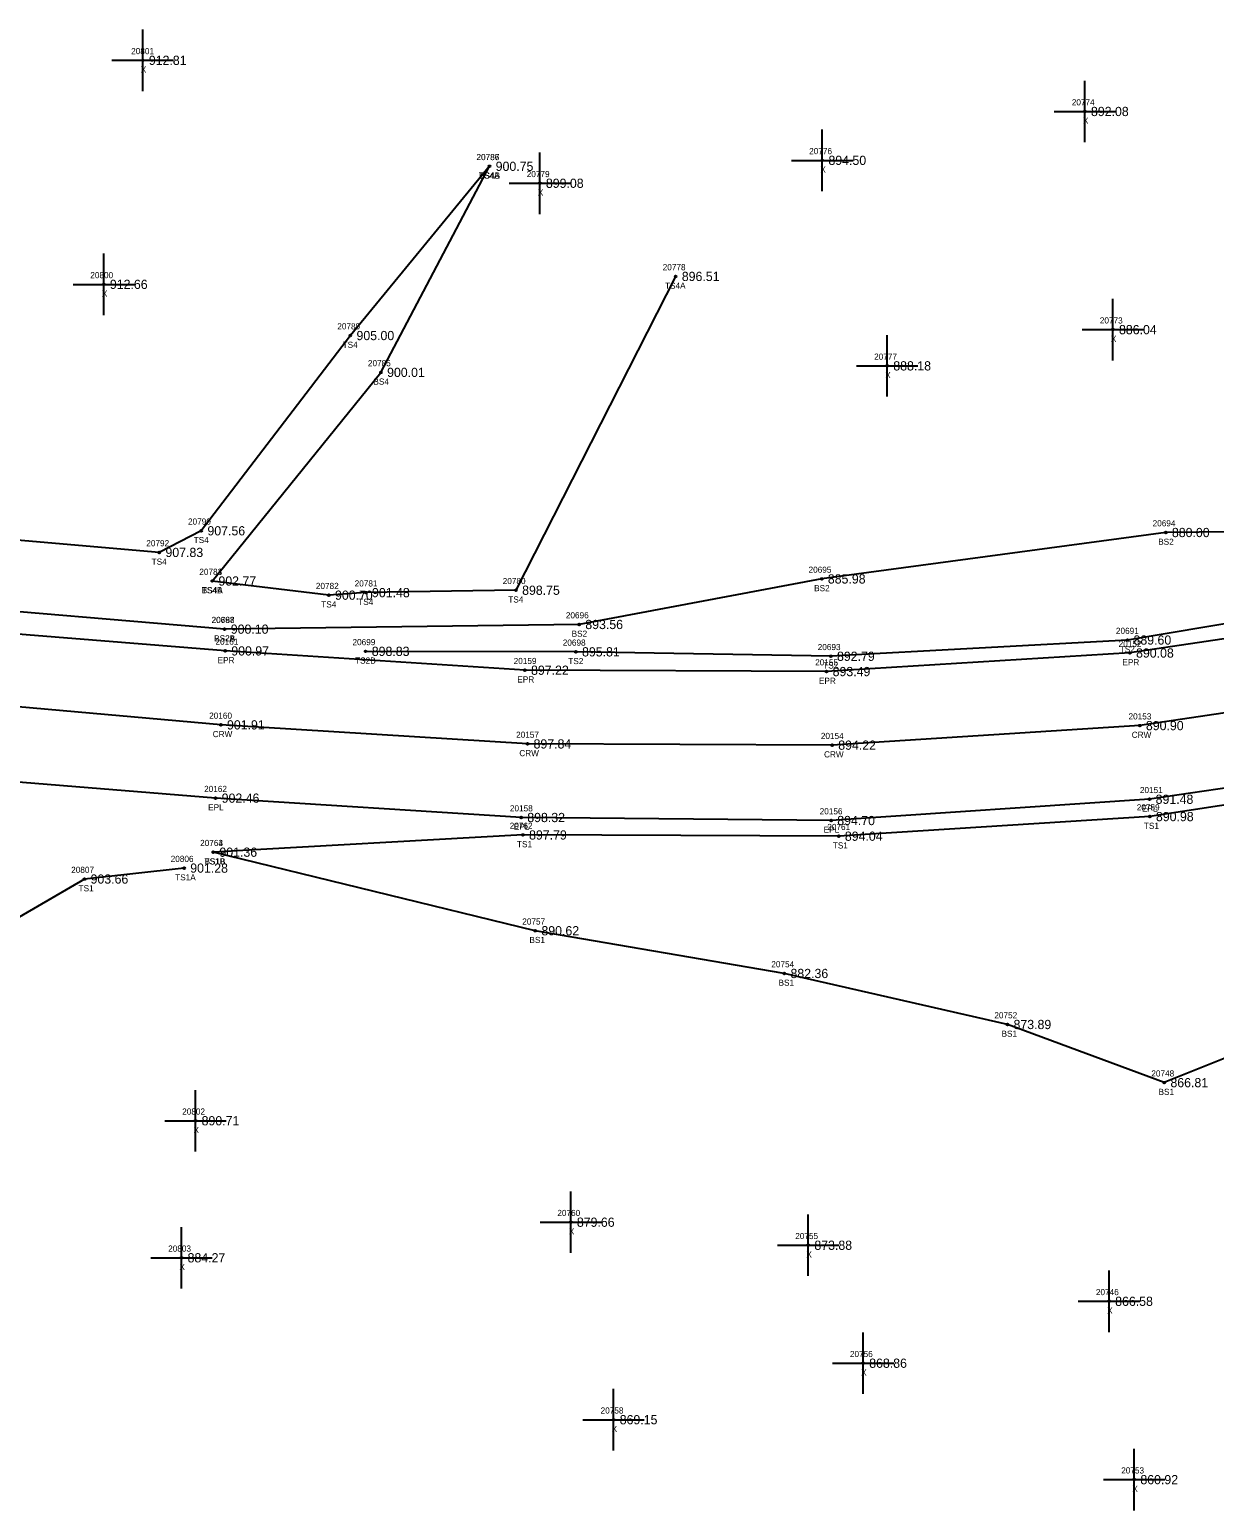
# Model space of a CAD drawing. Extents: x 1394668 to 1397182, y 1073212 to 1074501.
# Drawn here: x 1395039.9 to 1395232.7, y 1073240.6 to 1073481.5 of the extents above; entities that cross this region are included whole.
import ezdxf

# ---------------------------------------------------------------- set-up
doc = ezdxf.new("R2010")
doc.units = 0
for name, color, linetype in [('RD_DTM_BkLn1', 7, 'Continuous'), ('RD_DTM_BkLn2', 7, 'Continuous'), ('RD_DTM_BkLn_txCode', 7, 'Continuous'), ('RD_EX_Misc', 7, 'Continuous'), ('RD_EX_Misc_txCode', 7, 'Continuous'), ('RD_EX_Road', 7, 'Continuous'), ('RD_EX_Road_txCode', 7, 'Continuous'), ('RD_EX_TX_Misc_ELEV', 7, 'Continuous'), ('RD_EX_TX_Road_ELEV', 7, 'Continuous'), ('RD_HC_Survey_ELEV', 7, 'Continuous'), ('RD_HC_Survey_txCode', 7, 'Continuous'), ('RD_SMD_Locator', 7, 'Continuous')]:
    doc.layers.add(name, color=color, linetype=linetype)

msp = doc.modelspace()

# ---------------------------------------------------------------- linework, layer by layer
at = {"layer": 'RD_DTM_BkLn1'}
msp.add_lwpolyline([(1395269.86, 1073375.63), (1395220.56, 1073368.3), (1395170.5, 1073365.12), (1395120.93, 1073365.32), (1395071.05, 1073368.42), (1395021.54, 1073372.81), (1394971.87, 1073376.94), (1394922.47, 1073381.05), (1394872.44, 1073385.42), (1394823.01, 1073389.97), (1394773.09, 1073394.98), (1394723.98, 1073400.02), (1394673.96, 1073406.13)], dxfattribs=at)
at = {"layer": 'RD_DTM_BkLn2'}
for points in [[(1395114.77, 1073459.28), (1395092.12, 1073431.75), (1395067.87, 1073399.99), (1395061.04, 1073396.47), (1395025.37, 1073399.56), (1394974.8, 1073407.99), (1394931.77, 1073413.87), (1394889.66, 1073418.67), (1394830.32, 1073422.7), (1394776.13, 1073426.07), (1394727.84, 1073425.98), (1394677.73, 1073438.51)], [(1395069.66, 1073391.82), (1395097.1, 1073425.76), (1395114.77, 1073459.28)], [(1395145.05, 1073441.37), (1395119.07, 1073390.32), (1395094.65, 1073389.93), (1395088.63, 1073389.52), (1395069.66, 1073391.82)], [(1395417.91, 1073439.53), (1395361.72, 1073419.92), (1395311.79, 1073409.42), (1395260.95, 1073403.11), (1395235.63, 1073399.82), (1395224.79, 1073399.71), (1395168.81, 1073392.16), (1395129.35, 1073384.75), (1395071.67, 1073383.99)], [(1395417.91, 1073439.53), (1395362.92, 1073415.49), (1395315.05, 1073400.56), (1395264.37, 1073389.89), (1395218.54, 1073382.22), (1395170.3, 1073379.58), (1395128.82, 1073380.3), (1395094.61, 1073380.38)], [(1395473.36, 1073426.66), (1395445.06, 1073409.89), (1395422.33, 1073386.84), (1395379.99, 1073368.17), (1395331.06, 1073356.38), (1395283.99, 1073330.88), (1395245.7, 1073318.7), (1395224.55, 1073310.22), (1395199.02, 1073319.68), (1395162.73, 1073327.98), (1395122.21, 1073334.93), (1395069.82, 1073347.71)], [(1395071.67, 1073383.99), (1395022.85, 1073388.1), (1394972.66, 1073392.81), (1394924.06, 1073396.78), (1394873.93, 1073401.64), (1394823.64, 1073405.87), (1394773.54, 1073410.91), (1394725.43, 1073416.05), (1394673.91, 1073423.25)], [(1395452.31, 1073419.59), (1395417.25, 1073404.2), (1395370.51, 1073387.46), (1395323.17, 1073373.09), (1395272.12, 1073361.17), (1395222.19, 1073353.5), (1395171.58, 1073350.31), (1395120.2, 1073350.51), (1395069.82, 1073347.71)], [(1395065.07, 1073345.12), (1395048.86, 1073343.34), (1395018.25, 1073325.55), (1394979.28, 1073305.47), (1394947.11, 1073294.37), (1394924.89, 1073288.06), (1394884.19, 1073296.87), (1394821.51, 1073309.12), (1394774.98, 1073327.05), (1394739.84, 1073344.19), (1394711.9, 1073363.27), (1394701.45, 1073376.62)]]:
    msp.add_lwpolyline(points, dxfattribs=at)
at = {"layer": 'RD_EX_Misc'}
for p, q in [((1395058.34, 1073471.52), (1395058.34, 1073481.52)), ((1395053.34, 1073476.52), (1395063.34, 1073476.52)), ((1395211.62, 1073463.2), (1395211.62, 1073473.2)), ((1395206.62, 1073468.2), (1395216.62, 1073468.2)), ((1395168.91, 1073455.25), (1395168.91, 1073465.25)), ((1395122.94, 1073451.52), (1395122.94, 1073461.52)), ((1395163.91, 1073460.25), (1395173.91, 1073460.25)), ((1395117.94, 1073456.52), (1395127.94, 1073456.52)), ((1395052, 1073435.08), (1395052, 1073445.08)), ((1395047, 1073440.08), (1395057, 1073440.08)), ((1395216.18, 1073427.71), (1395216.18, 1073437.71)), ((1395179.46, 1073421.82), (1395179.46, 1073431.82)), ((1395211.18, 1073432.71), (1395221.18, 1073432.71)), ((1395174.46, 1073426.82), (1395184.46, 1073426.82)), ((1395066.92, 1073299.02), (1395066.92, 1073309.02)), ((1395061.92, 1073304.02), (1395071.92, 1073304.02)), ((1395127.98, 1073282.52), (1395127.98, 1073292.52)), ((1395122.98, 1073287.52), (1395132.98, 1073287.52)), ((1395166.62, 1073278.77), (1395166.62, 1073288.77)), ((1395064.64, 1073276.73), (1395064.64, 1073286.73)), ((1395161.62, 1073283.77), (1395171.62, 1073283.77)), ((1395059.64, 1073281.73), (1395069.64, 1073281.73)), ((1395215.56, 1073269.65), (1395215.56, 1073279.65)), ((1395210.56, 1073274.65), (1395220.56, 1073274.65)), ((1395175.54, 1073259.58), (1395175.54, 1073269.58)), ((1395170.54, 1073264.58), (1395180.54, 1073264.58)), ((1395134.95, 1073250.39), (1395134.95, 1073260.39)), ((1395129.95, 1073255.39), (1395139.95, 1073255.39)), ((1395219.66, 1073240.64), (1395219.66, 1073250.64)), ((1395214.66, 1073245.64), (1395224.66, 1073245.64))]:
    msp.add_line(p, q, dxfattribs=at)
at = {"layer": 'RD_EX_Road'}
for points in [[(1395267.16, 1073387.31), (1395218.96, 1073380.11), (1395169.59, 1073377.09), (1395120.52, 1073377.31), (1395071.75, 1073380.45), (1395022.48, 1073384.43), (1394972.65, 1073388.56), (1394922.93, 1073392.96), (1394872.57, 1073397.27), (1394823.93, 1073401.93), (1394774.03, 1073406.64), (1394724.37, 1073412.09), (1394676.23, 1073417.71)], [(1395271.04, 1073363.5), (1395222.14, 1073356.32), (1395170.34, 1073352.86), (1395119.91, 1073353.35), (1395070.19, 1073356.5), (1395020.02, 1073360.58), (1394970.69, 1073365), (1394920.93, 1073369.48), (1394871.71, 1073374.33), (1394821.21, 1073378.78), (1394772.49, 1073383.81), (1394722.62, 1073388.78), (1394672.88, 1073394.93)]]:
    msp.add_lwpolyline(points, dxfattribs=at)
at = {"layer": 'RD_SMD_Locator'}
for centre in [(1395058.34, 1073476.52), (1395211.62, 1073468.2), (1395168.91, 1073460.25), (1395114.77, 1073459.28), (1395114.77, 1073459.28), (1395122.94, 1073456.52), (1395145.05, 1073441.37), (1395052, 1073440.08), (1395092.12, 1073431.75), (1395216.18, 1073432.71), (1395179.46, 1073426.82), (1395097.1, 1073425.76), (1395067.87, 1073399.99), (1395224.79, 1073399.71), (1395061.04, 1073396.47), (1395069.66, 1073391.82), (1395069.66, 1073391.82), (1395168.81, 1073392.16), (1395088.63, 1073389.52), (1395094.65, 1073389.93), (1395119.07, 1073390.32), (1395071.67, 1073383.99), (1395071.67, 1073383.99), (1395129.35, 1073384.75), (1395218.54, 1073382.22), (1395071.75, 1073380.45), (1395094.61, 1073380.38), (1395128.82, 1073380.3), (1395170.3, 1073379.58), (1395218.96, 1073380.11), (1395120.52, 1073377.31), (1395169.59, 1073377.09), (1395071.05, 1073368.42), (1395220.56, 1073368.3), (1395120.93, 1073365.32), (1395170.5, 1073365.12), (1395070.19, 1073356.5), (1395222.14, 1073356.32), (1395119.91, 1073353.35), (1395170.34, 1073352.86), (1395222.19, 1073353.5), (1395120.2, 1073350.51), (1395171.58, 1073350.31), (1395069.82, 1073347.71), (1395069.82, 1073347.71), (1395065.07, 1073345.12), (1395048.86, 1073343.34), (1395122.21, 1073334.93), (1395162.73, 1073327.98), (1395199.02, 1073319.68), (1395224.55, 1073310.22), (1395066.92, 1073304.02), (1395127.98, 1073287.52), (1395166.62, 1073283.77), (1395064.64, 1073281.73), (1395215.56, 1073274.65), (1395175.54, 1073264.58), (1395134.95, 1073255.39), (1395219.66, 1073245.64)]:
    msp.add_circle(centre, 0.15, dxfattribs=at)

# ---------------------------------------------------------------- texts
at = {"layer": 'RD_DTM_BkLn_txCode'}
for s, p in [('20786', (1395112.63, 1073460.28)), ('20787', (1395112.65, 1073460.28)), ('TS4A', (1395113.04, 1073457.28)), ('BS4B', (1395113.07, 1073457.28)), ('20778', (1395142.94, 1073442.37)), ('TS4A', (1395143.32, 1073439.37)), ('20789', (1395090, 1073432.75)), ('TS4', (1395090.87, 1073429.75)), ('20785', (1395094.98, 1073426.76)), ('BS4', (1395095.87, 1073423.76)), ('20790', (1395065.71, 1073400.99)), ('20694', (1395222.65, 1073400.71)), ('20792', (1395058.92, 1073397.47)), ('TS4', (1395066.63, 1073397.99)), ('BS2', (1395223.56, 1073397.71)), ('TS4', (1395059.79, 1073394.47)), ('20783', (1395067.55, 1073392.82)), ('20784', (1395067.55, 1073392.82)), ('20695', (1395166.67, 1073393.16)), ('TS4B', (1395067.95, 1073389.82)), ('BS4A', (1395067.95, 1073389.82)), ('20782', (1395086.51, 1073390.52)), ('20781', (1395092.82, 1073390.93)), ('20780', (1395116.91, 1073391.32)), ('BS2', (1395167.58, 1073390.16)), ('TS4', (1395087.39, 1073387.52)), ('TS4', (1395093.41, 1073387.93)), ('TS4', (1395117.82, 1073388.32)), ('20697', (1395069.53, 1073384.99)), ('20788', (1395069.56, 1073384.99)), ('20696', (1395127.18, 1073385.75)), ('BS2', (1395128.12, 1073382.75)), ('20691', (1395216.68, 1073383.22)), ('BS2A', (1395069.96, 1073381.99)), ('BS2B', (1395069.97, 1073381.99)), ('20699', (1395092.47, 1073381.38)), ('20698', (1395126.68, 1073381.3)), ('20693', (1395168.16, 1073380.58)), ('TS2', (1395217.3, 1073380.22)), ('TS2B', (1395092.9, 1073378.38)), ('TS2', (1395127.58, 1073378.3)), ('TS2', (1395169.06, 1073377.58)), ('20759', (1395220.07, 1073354.5)), ('20762', (1395118.05, 1073351.51)), ('20761', (1395169.72, 1073351.31)), ('TS1', (1395221.23, 1073351.5)), ('20763', (1395067.68, 1073348.71)), ('20764', (1395067.68, 1073348.71)), ('20806', (1395062.89, 1073346.12)), ('TS1', (1395119.23, 1073348.51)), ('TS1', (1395170.62, 1073348.31)), ('20807', (1395046.7, 1073344.34)), ('TS1B', (1395068.39, 1073345.71)), ('BS1B', (1395068.4, 1073345.71)), ('TS1', (1395047.9, 1073341.34)), ('TS1A', (1395063.62, 1073343.12)), ('20757', (1395120.09, 1073335.93)), ('BS1', (1395121.26, 1073332.93)), ('20754', (1395160.61, 1073328.98)), ('BS1', (1395161.79, 1073325.98)), ('20752', (1395196.9, 1073320.68)), ('BS1', (1395198.07, 1073317.68)), ('20748', (1395222.44, 1073311.22)), ('BS1', (1395223.61, 1073308.22))]:
    msp.add_text(s, height=1, dxfattribs=at).set_placement(p)
at = {"layer": 'RD_EX_Misc_txCode'}
for s, p in [('20801', (1395056.46, 1073477.52)), ('X', (1395058.02, 1073474.52)), ('20774', (1395209.5, 1073469.2)), ('X', (1395211.31, 1073466.2)), ('20776', (1395166.77, 1073461.25)), ('20779', (1395120.82, 1073457.52)), ('X', (1395168.59, 1073458.25)), ('X', (1395122.62, 1073454.52)), ('20800', (1395049.81, 1073441.08)), ('X', (1395051.69, 1073438.08)), ('20773', (1395214.06, 1073433.71)), ('X', (1395215.86, 1073430.71)), ('20777', (1395177.34, 1073427.82)), ('X', (1395179.15, 1073424.82)), ('20802', (1395064.76, 1073305.02)), ('X', (1395066.61, 1073302.02)), ('20760', (1395125.8, 1073288.52)), ('X', (1395127.67, 1073285.52)), ('20755', (1395164.5, 1073284.77)), ('20803', (1395062.48, 1073282.73)), ('X', (1395166.31, 1073281.77)), ('X', (1395064.32, 1073279.73)), ('20746', (1395213.42, 1073275.65)), ('X', (1395215.25, 1073272.65)), ('20756', (1395173.4, 1073265.58)), ('X', (1395175.23, 1073262.58)), ('20758', (1395132.84, 1073256.39)), ('X', (1395134.64, 1073253.39)), ('20753', (1395217.54, 1073246.64)), ('X', (1395219.35, 1073243.64))]:
    msp.add_text(s, height=1, dxfattribs=at).set_placement(p)
at = {"layer": 'RD_EX_Road_txCode'}
for s, p in [('20161', (1395070.18, 1073381.45)), ('20152', (1395217.12, 1073381.11)), ('EPR', (1395070.52, 1073378.45)), ('20159', (1395118.69, 1073378.31)), ('20155', (1395167.75, 1073378.09)), ('EPR', (1395217.73, 1073378.11)), ('EPR', (1395119.29, 1073375.31)), ('EPR', (1395168.36, 1073375.09)), ('20162', (1395068.33, 1073357.5)), ('20151', (1395220.58, 1073357.32)), ('EPL', (1395068.98, 1073354.5)), ('20158', (1395118.08, 1073354.35)), ('20156', (1395168.48, 1073353.86)), ('EPL', (1395220.93, 1073354.32)), ('EPL', (1395118.71, 1073351.35)), ('EPL', (1395169.13, 1073350.86))]:
    msp.add_text(s, height=1, dxfattribs=at).set_placement(p)
at = {"layer": 'RD_EX_TX_Misc_ELEV'}
for s, p in [('912.81', (1395059.34, 1073475.77)), ('892.08', (1395212.62, 1073467.45)), ('894.50', (1395169.91, 1073459.5)), ('900.75', (1395115.77, 1073458.53)), ('900.75', (1395115.77, 1073458.53)), ('899.08', (1395123.94, 1073455.77)), ('896.51', (1395146.05, 1073440.62)), ('912.66', (1395053, 1073439.33)), ('905.00', (1395093.12, 1073431)), ('886.04', (1395217.18, 1073431.96)), ('888.18', (1395180.46, 1073426.07)), ('900.01', (1395098.1, 1073425.01)), ('907.56', (1395068.87, 1073399.24)), ('880.00', (1395225.79, 1073398.96)), ('907.83', (1395062.04, 1073395.72)), ('885.98', (1395169.81, 1073391.41)), ('902.77', (1395070.66, 1073391.07)), ('902.77', (1395070.66, 1073391.07)), ('901.48', (1395095.65, 1073389.18)), ('898.75', (1395120.07, 1073389.57)), ('900.70', (1395089.63, 1073388.77)), ('900.10', (1395072.67, 1073383.24)), ('900.10', (1395072.67, 1073383.24)), ('893.56', (1395130.35, 1073384)), ('898.83', (1395095.61, 1073379.63)), ('895.81', (1395129.82, 1073379.55)), ('889.60', (1395219.54, 1073381.47)), ('892.79', (1395171.3, 1073378.83)), ('890.98', (1395223.19, 1073352.75)), ('897.79', (1395121.2, 1073349.76)), ('894.04', (1395172.58, 1073349.56)), ('901.36', (1395070.82, 1073346.96)), ('901.36', (1395070.82, 1073346.96)), ('901.28', (1395066.07, 1073344.37)), ('903.66', (1395049.86, 1073342.59)), ('890.62', (1395123.21, 1073334.18)), ('882.36', (1395163.73, 1073327.23)), ('873.89', (1395200.02, 1073318.93)), ('866.81', (1395225.55, 1073309.47)), ('890.71', (1395067.92, 1073303.27)), ('879.66', (1395128.98, 1073286.77)), ('873.88', (1395167.62, 1073283.02)), ('884.27', (1395065.64, 1073280.98)), ('866.58', (1395216.56, 1073273.9)), ('868.86', (1395176.54, 1073263.83)), ('869.15', (1395135.95, 1073254.64)), ('860.92', (1395220.66, 1073244.89))]:
    msp.add_text(s, height=1.5, dxfattribs=at).set_placement(p)
at = {"layer": 'RD_EX_TX_Road_ELEV'}
for s, p in [('900.97', (1395072.75, 1073379.7)), ('890.08', (1395219.96, 1073379.36)), ('897.22', (1395121.52, 1073376.56)), ('893.49', (1395170.59, 1073376.34)), ('902.46', (1395071.19, 1073355.75)), ('891.48', (1395223.14, 1073355.57)), ('898.32', (1395120.91, 1073352.6)), ('894.70', (1395171.34, 1073352.11))]:
    msp.add_text(s, height=1.5, dxfattribs=at).set_placement(p)
at = {"layer": 'RD_HC_Survey_ELEV'}
for s, p in [('901.91', (1395072.05, 1073367.67)), ('890.90', (1395221.56, 1073367.55)), ('897.84', (1395121.93, 1073364.57)), ('894.22', (1395171.5, 1073364.37))]:
    msp.add_text(s, height=1.5, dxfattribs=at).set_placement(p)
at = {"layer": 'RD_HC_Survey_txCode'}
for s, p in [('20160', (1395069.15, 1073369.42)), ('20153', (1395218.73, 1073369.3)), ('CRW', (1395069.73, 1073366.42)), ('20157', (1395119.09, 1073366.32)), ('20154', (1395168.67, 1073366.12)), ('CRW', (1395219.25, 1073366.3)), ('CRW', (1395119.61, 1073363.32)), ('CRW', (1395169.19, 1073363.12))]:
    msp.add_text(s, height=1, dxfattribs=at).set_placement(p)

doc.saveas('drawing.dxf')
